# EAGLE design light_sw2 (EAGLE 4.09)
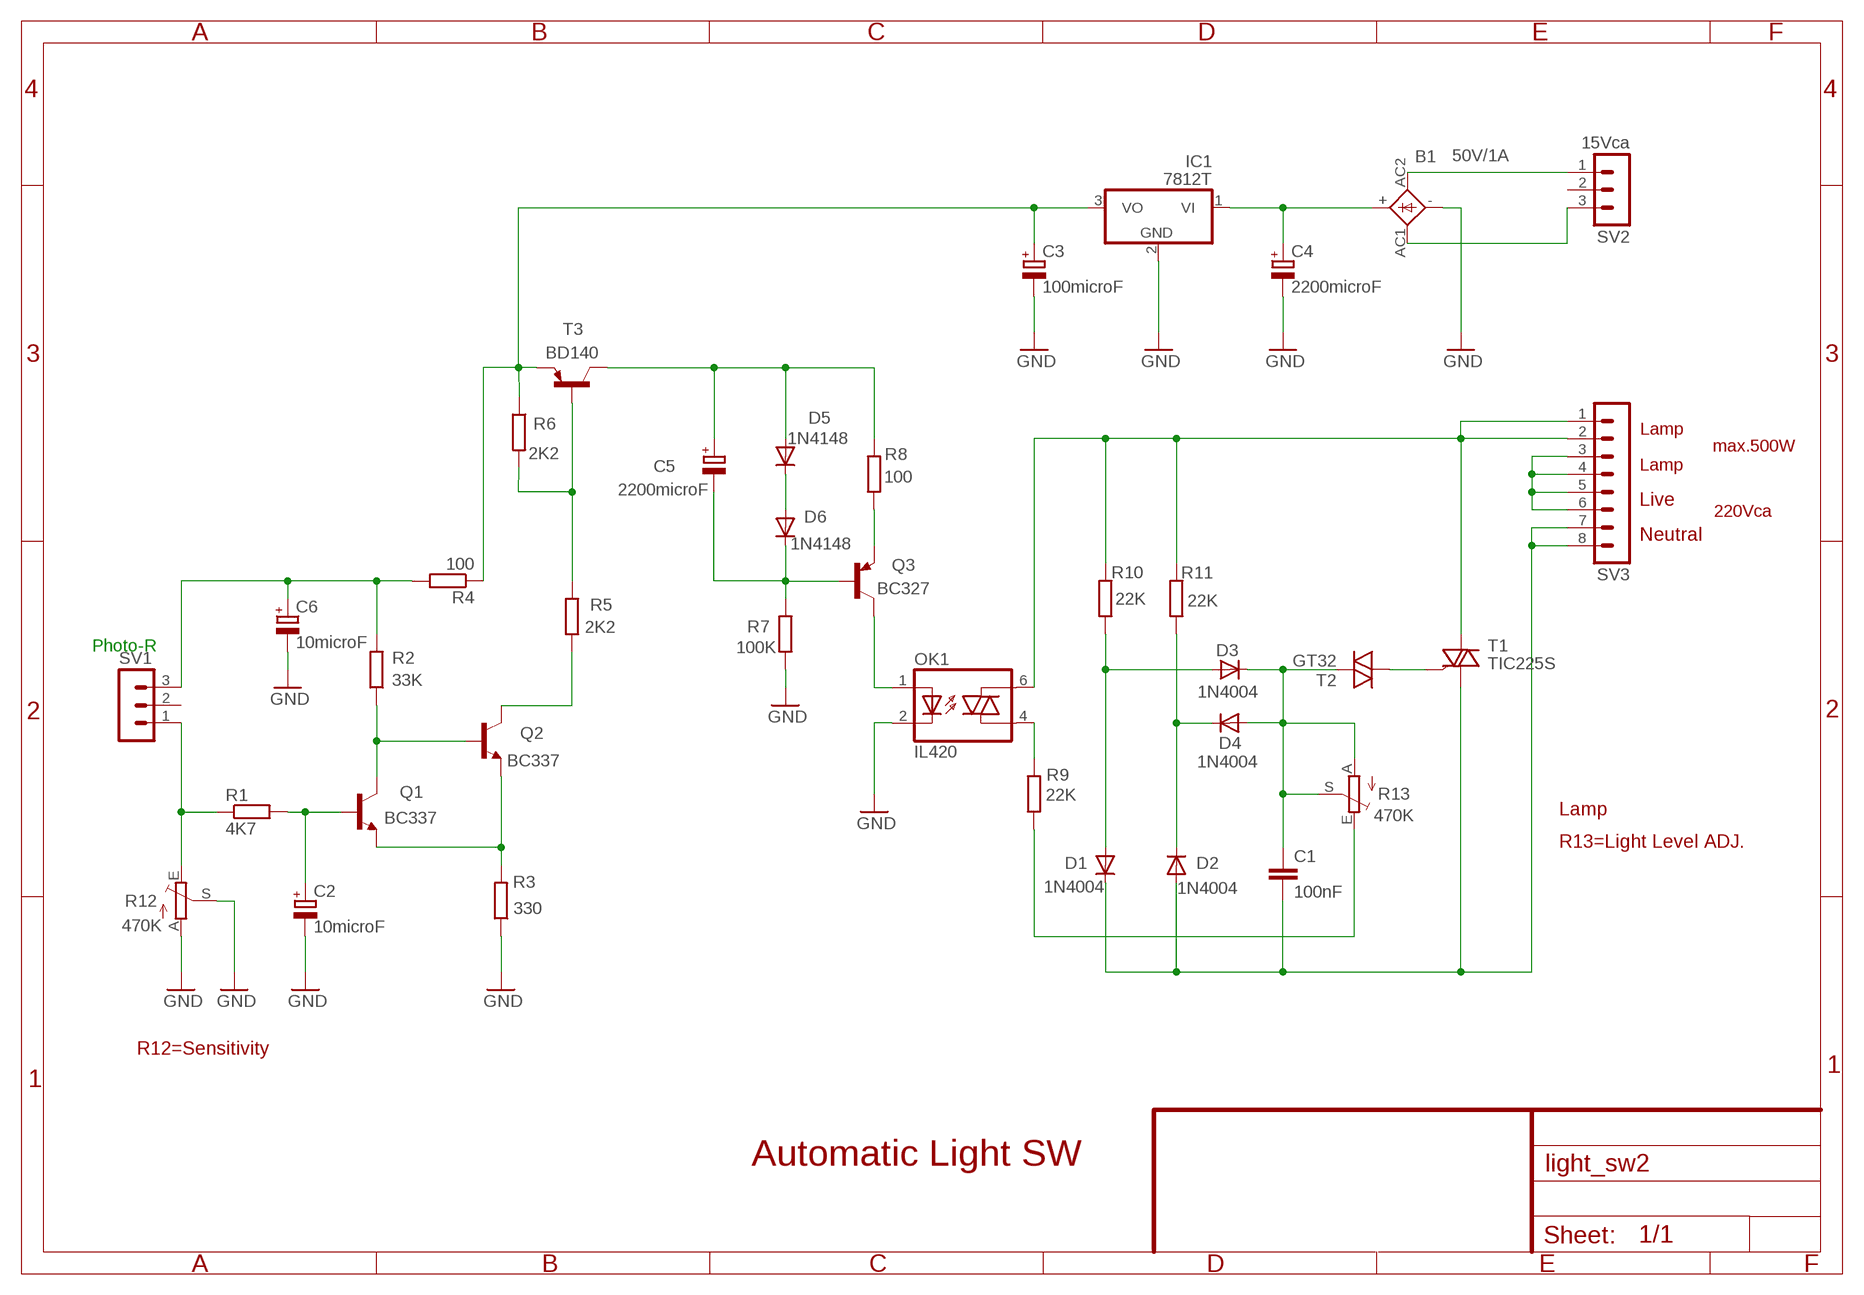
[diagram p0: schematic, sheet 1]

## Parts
B1  50V/1A  2KBP  [2KBP]
C1  100nF  C-EU050-045X075  [C050-045X075]
C2  10microF  CPOL-EUB45181A  [B45181A]
C3  100microF  CPOL-EUB45181A  [B45181A]
C4  2200microF  CPOL-EUB45181D  [B45181D]
C5  2200microF  CPOL-EUB45181D  [B45181D]
C6  10microF  CPOL-EUB45181A  [B45181A]
D1  1N4004  [DO41-10]
D2  1N4004  [DO41-10]
D3  1N4004  [DO41-10]
D4  1N4004  [DO41-10]
D5  1N4148  [DO35-10]
D6  1N4148  [DO35-10]
IC1  7812T  [TO220H]
OK1  IL420  [DIL06]
Q1  BC337  [TO92]
Q2  BC337  [TO92]
Q3  BC327  [TO92-EBC]
R1  4K7  R-EU_0207/7  [0207/7]
R2  33K  R-EU_0207/7  [0207/7]
R3  330  R-EU_0207/7  [0207/7]
R4  100  R-EU_0207/7  [0207/7]
R5  2K2  R-EU_0207/7  [0207/7]
R6  2K2  R-EU_0207/7  [0207/7]
R7  100K  R-EU_0207/7  [0207/7]
R8  100  R-EU_0207/7  [0207/7]
R9  22K  R-EU_0207/7  [0207/7]
R10  22K  R-EU_0207/7  [0207/7]
R11  22K  R-EU_0207/7  [0207/7]
R12  470K  TRIM_EU-LI10  [LI10]
R13  470K  TRIM_EU-LI10  [LI10]
SV1  MA03-1  [MA03-1]
SV2  15Vca  MA03-1  [MA03-1]
SV3  MA08-1  [MA08-1]
T1  TIC225S  [TO220DS]
T2  GT32  [GT32]
T3  BD140  [TO126]

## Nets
GND: B1.- C2.- C3.- C4.- C6.- IC1.2(GND) OK1.2(C) R3.1 R7.1 R12.A R12.S
N$1: C6.+ R2.2 R4.2 SV1.3
N$2: Q1.3(C) Q2.2(B) R2.1
N$3: Q2.3(C) R5.2
N$4: R5.1 R6.2 T3.3(B)
N$5: C3.+ IC1.3(VO) R4.1 R6.1 T3.1(E)
N$6: Q1.1(E) Q2.1(E) R3.2
N$7: C2.+ Q1.2(B) R1.2
N$8: R1.1 R12.E SV1.1
N$9: OK1.6(A2) R10.2 R11.2 SV3.1 SV3.2 T1.A2
N$10: SV3.3 SV3.4 SV3.5 SV3.6
N$11: B1.+ C4.+ IC1.1(VI)
N$13: B1.AC2 SV2.1
N$14: B1.AC1 SV2.3
N$15: T1.G T2.1
N$16: C5.+ D5.A R8.2 T3.2(C)
N$17: D5.C D6.A
N$18: Q3.E R8.1
N$19: C5.- D6.C Q3.B R7.2
N$20: OK1.1(A) Q3.C
N$21: OK1.4(A1) R9.2
N$22: D1.A D3.A R10.1
N$23: D2.C D4.C R11.1
N$24: C1.1 D3.C D4.A R13.A R13.S T2.2
N$25: R9.1 R13.E
N$26: C1.2 D1.C D2.A SV3.7 SV3.8 T1.A1
Unconnected: SV1.2 SV2.2

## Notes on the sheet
- Lamp
- max.500W
- Lamp
- Live
- 220Vca
- Neutral
- Photo-R
- Lamp
- R13=Light Level ADJ.
- R12=Sensitivity
- Automatic Light SW

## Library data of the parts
B1 = rectifier:2KBP: RECTIFIER grid 3 x 3,81 mm
C1 = rcl:C-EU: CAPACITOR, European symbol
C2-C6 = rcl:CPOL-EU: POLARIZED CAPACITOR, European symbol
D1-D4 = diode:1N4004: DIODE
D5 D6 = diode:1N4148: DIODE
IC1 = linear:78*: Positive VOLTAGE REGULATOR
OK1 = optocoupler:IL420: SIEMENS OPTO COUPLER
Q1 Q2 = transistor-npn:BC337*: NPN Transistor
Q3 = transistor-pnp:BC327*: PNP Transistror
R1-R11 = rcl:R-EU_: RESISTOR, European symbol
R12 R13 = pot:TRIM_EU-: POTENTIOMETER
SV1 SV2 = con-lstb:MA03-1: PIN HEADER
SV3 = con-lstb:MA08-1: PIN HEADER
T1 = triac:TIC225S: TRIAC
T2 = triac:GT32: TRIGGER DIODE
T3 = transistor-pnp:BD140: PNP Transistor

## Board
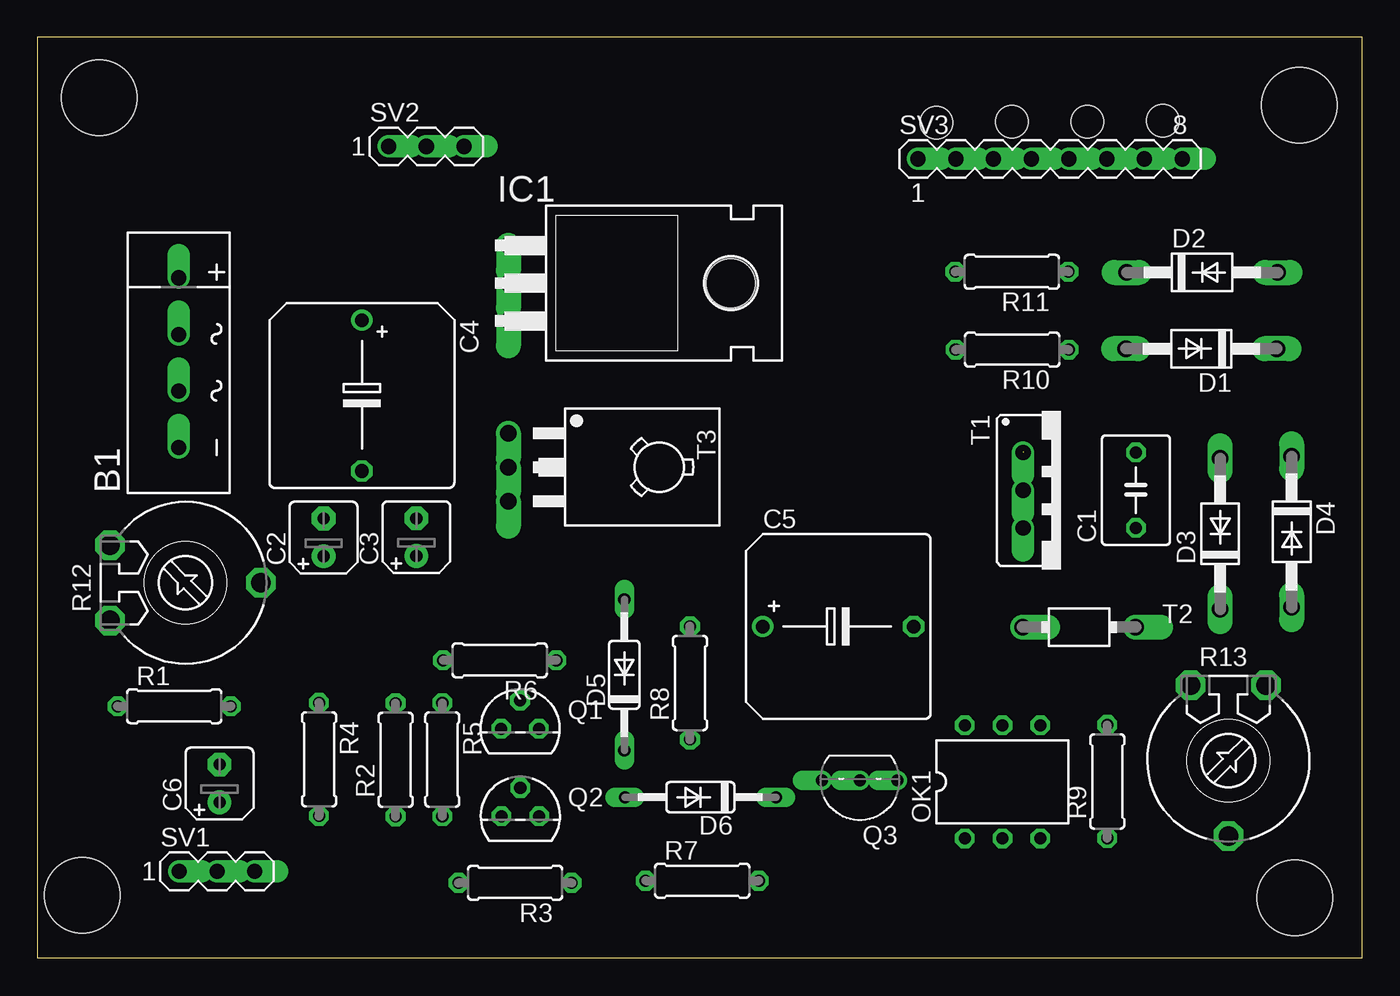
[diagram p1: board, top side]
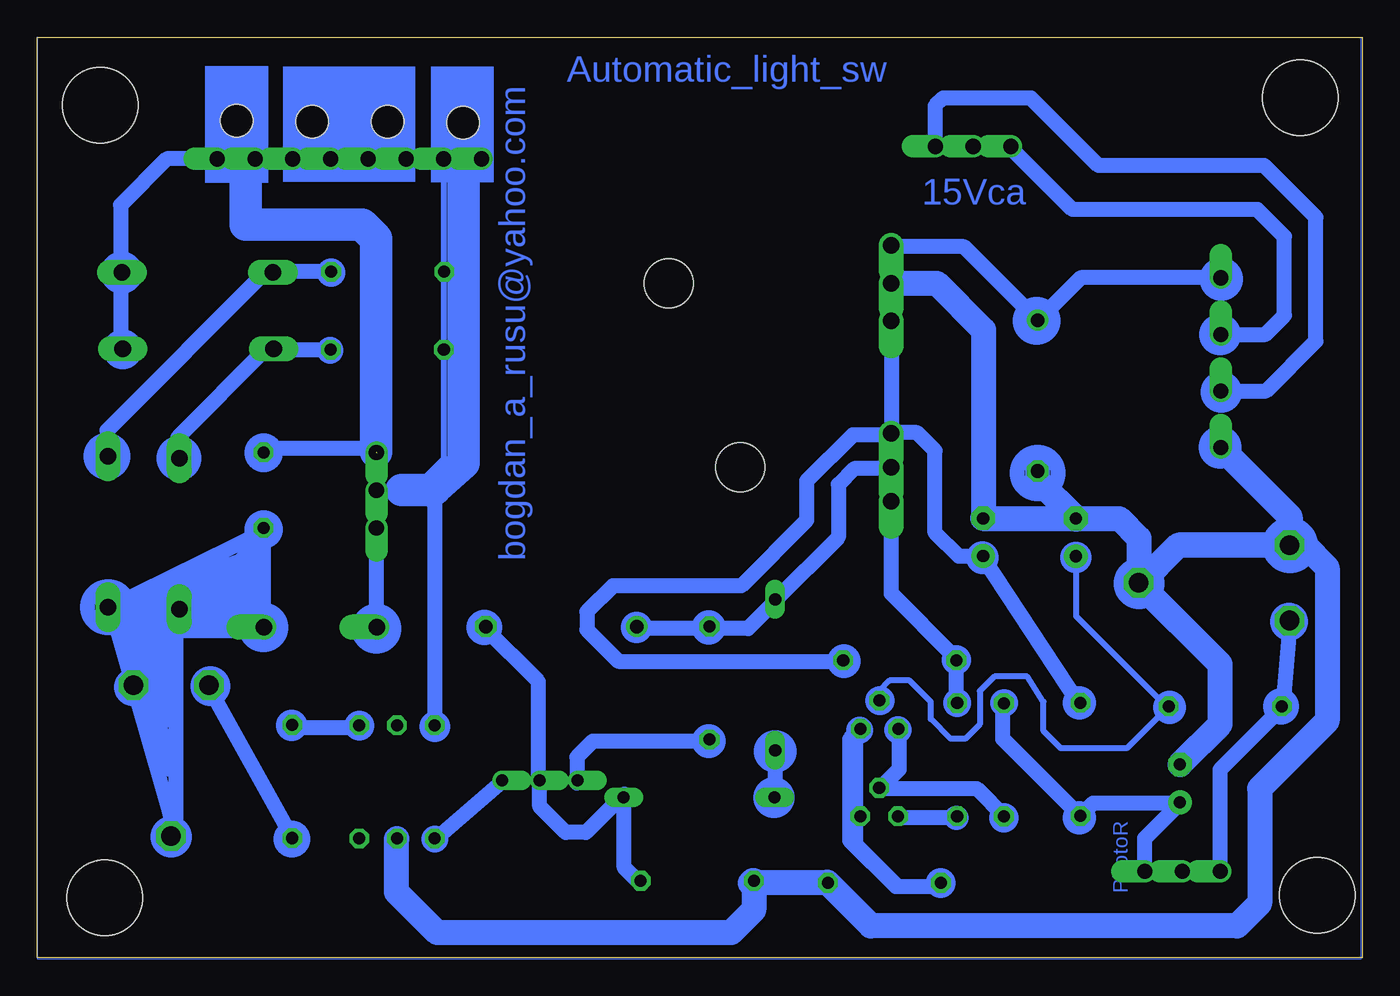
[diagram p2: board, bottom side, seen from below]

Size 89.23 x 61.98 mm. Coordinates in mm from the lower left corner, seen from the top.
Outline: 0,0 89.23,0 89.23,61.98 0,61.98 0,0
Copper layers used: Bottom
Holes 5.08 mm at 4.19,57.91 84.97,57.42 3.04,4.21 84.68,4.06
Holes 2.18 mm at 60.55,56.24 65.64,56.31 70.72,56.31 75.8,56.39

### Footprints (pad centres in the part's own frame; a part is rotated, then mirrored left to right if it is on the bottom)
2KBP = drill 1.016 offset: + 5.715,0; - -5.715,0; AC1 -1.905,0; AC2 1.905,0
C050-045X075 = drill 0.813 octagon: 1 -2.54,0; 2 2.54,0
B45181A = drill 0.813 pad 1.6 round: + -1.27,0 | drill 0.813 pad 1.6 octagon: - 1.27,0
B45181D = drill 0.914 round: + -5.08,0 | drill 0.914 octagon: - 5.08,0
DO41-10 = drill 1.118 long: A 5.08,0; C -5.08,0
DO35-10 = drill 0.813 long: A 5.08,0; C -5.08,0
TO220H = drill 1.118 offset: 1 -2.54,-10.16; 2 0,-10.16; 3 2.54,-10.16 | hole 3.302: 0,4.826
DIL06 = drill 0.813 octagon: 1 -2.54,-3.81; 2 0,-3.81; 3 2.54,-3.81; 4 2.54,3.81; 5 0,3.81; 6 -2.54,3.81
TO92 = drill 0.813 octagon: 1 1.27,0; 2 0,1.905; 3 -1.27,0
TO92-EBC = drill 0.813 offset: B 0,-1.27; C -2.54,-1.27; E 2.54,-1.27
0207/7 = drill 0.813 octagon: 1 -3.81,0; 2 3.81,0
LI10 = drill 1.321 octagon: A -2.54,-5.08; E 2.54,-5.08; S 0,5.08
MA03-1 = drill 1.016 offset: 1 -2.54,0; 2 0,0; 3 2.54,0
MA08-1 = drill 1.016 offset: 1 -8.89,0; 2 -6.35,0; 3 -3.81,0; 4 -1.27,0; 5 1.27,0; 6 3.81,0; 7 6.35,0; 8 8.89,0
TO220DS = drill 1.016 offset: A1 -2.54,-2.54; A2 0,-2.54; G 2.54,-2.54
GT32 = drill 1.118 offset: 1 -3.81,0; 2 3.81,0
TO126 = drill 1.118 offset: 1 -2.286,-5.08; 2 0,-5.08; 3 2.286,-5.08 | hole 3.302: 0,5.08

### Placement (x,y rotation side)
B1  9.54,40.08 90 top
C1  73.98,31.5 90 top
C2  19.28,28.31 90 top
C3  25.53,28.33 90 top
C4  21.87,37.86 270 top
C5  53.94,22.31 0 top
C6  12.28,11.75 90 top
D1  78.39,41.02 180 top
D2  78.44,46.16 0 top
D3  79.65,28.56 90 top
D4  84.47,28.69 270 top
D5  39.53,19.06 90 top
D6  44.66,10.82 180 top
IC1  41.89,45.43 270 top
OK1  65,11.85 0 top
Q1  32.52,15.43 0 top
Q2  32.53,9.54 0 top
Q3  55.39,10.67 180 top
R1  9.23,16.95 0 top
R2  24.14,13.34 90 top
R3  32.18,5.05 180 top
R4  18.98,13.37 270 top
R5  27.28,13.35 270 top
R6  31.14,20.04 180 top
R7  44.78,5.19 0 top
R8  43.96,18.51 90 top
R9  72.05,11.88 90 top
R10  65.65,40.96 180 top
R11  65.62,46.2 180 top
R12  9.98,25.26 270 top
R13  80.21,13.28 180 top
SV1  12.11,5.83 0 top
SV2  26.2,54.64 0 top
SV3  68.21,53.8 0 top
T1  68.93,31.49 270 top
T2  70.16,22.27 0 top
T3  36.81,33.04 270 top

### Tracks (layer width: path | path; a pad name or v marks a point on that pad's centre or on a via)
GND
  Bottom 1.676: IC1.2 28.66,45.43 25.5,42.28 25.5,29.68 25.58,29.61 25.57,29.6 C3.- 19.35,29.6 19.28,29.53 19.28,29.54 C2.- | C2.- 16.38,29.58 15.04,28.24 15.04,25.21 | 15.04,25.21 15.06,25.24 R12.S | 15.04,25.21 14.96,25.13 | 4.87,27.71 4.87,27.77 | 4.87,27.77 R12.A 12.37,27.8 12.38,27.79 | B1.- 4.87,29.7 4.87,27.77 | R12.S 15.06,25.16 15.04,25.13 12.38,27.79 | C2.- 19.28,29.61 21.87,32.2 C4.- | R12.S 9.57,19.77 9.57,19.75 | C6.- 9.57,15.73 9.57,19.75 | 9.57,19.75 15.04,25.21 | 15.04,25.21 14.96,25.21 12.38,27.79 | 12.38,27.79 3.88,27.79 2.37,26.27 2.37,15.95 6.92,11.4 6.92,3.66 8.44,2.15 33.09,2.15 R3.1 | 36.05,5.11 R3.1 | R3.1 41.19,5.05 | 41.19,5.05 41.05,5.19 R7.1 40.97,3.22 42.5,1.69 62.3,1.69 65.03,4.42 65.03,7.99 65,8.02 OK1.2 | 41.19,5.05 41.21,5.03
N$1
  Bottom 0.406: SV1.3 14.65,8.18 12.32,10.51 C6.+ 18.04,10.48 18.98,9.53 | 19.03,9.49 18.98,9.53 | 18.98,9.53 R4.2 24.14,14.72 R2.2 | 24.14,17.18 R2.2 | R2.2
N$2
  Bottom 0.406: R2.1 26.05,11.45 Q2.2 31.24,12.74 Q1.3
N$3
  Bottom 0.406: Q2.3 31.23,9.51 27.32,9.51 R5.2
N$4
  Bottom 0.406: 27.34,20.06 R6.2 | R6.2 31.75,24.45 31.75,30.74 T3.3 | R5.1 27.28,20 R6.2
N$5
  Bottom 0.406: R4.1 25.6,27.07 C3.+ 27.31,27.06 28.75,28.5 28.75,34.04 30.04,35.33 31.71,35.33 31.73,35.31 | 31.74,35.3 31.73,35.31 | 31.73,35.31 T3.1 | 31.73,35.22 31.73,35.23 T3.1 | IC1.3 31.73,35.22 | 31.73,35.22 31.72,35.22 | R6.1 50.15,20.04 52.21,22.1 52.21,23.31 50.31,25.21 41.66,25.21 37.34,29.53 37.34,32.11 34.15,35.3 31.72,35.3 31.73,35.31 T3.1
  Bottom 1.016: 31.72,42.81 31.72,35.22 34.3,35.22 37.41,32.11 37.41,29.46 41.81,25.06 50.46,25.06 52.21,23.31 52.21,22.1 50.08,19.97 34.91,19.97
N$6
  Bottom 0.406: R3.2 31.1,5.05 33.79,7.74 33.79,9.55 Q2.1 33.8,15.31 33.79,15.33 Q1.1
N$7
  Bottom 0.406: C2.+ 19.28,23.02 13.07,16.8 13.04,16.83 R1.2 15.87,14.12 20.31,14.12 | 20.31,14.12 | 20.31,14.12 21.47,15.28 21.47,17.25 22.56,18.95 24.77,18.95 25.76,17.96 25.76,15.73 26.74,14.75 27.72,14.75 29.06,16.09 29.06,17.25 30.49,18.68 31.83,18.68 32.52,17.99 Q1.2
N$8
  Bottom 0.406: SV1.1 9.57,12.69 5.37,16.89 R1.1 4.81,22.6 R12.E
N$9
  Bottom 0.406: OK1.6 62.46,30.15 63.81,31.51 66.17,31.51 66.39,31.29 | 66.39,31.29 66.39,31.28 | 66.39,31.29 T1.A2 63.99,31.49 61.84,33.63 61.84,40.84 R10.2 | R10.2 61.84,46.22 | 61.84,46.22 | 61.77,53.8 61.77,53.81 | 61.77,53.8 SV3.2 59.19,53.8 | 61.84,46.22 61.84,53.73 61.77,53.8 | 59.19,53.8 SV3.1 | 59.19,53.8 59.19,53.81 | 61.79,46.2 61.77,46.22 | 61.79,46.2 R11.2 | R10.2 61.84,46.15 61.79,46.2
N$10
  Bottom 0.406: SV3.3 66.78,53.8 66.93,53.66 66.94,53.67 SV3.4 69.28,53.8 69.35,53.73 69.42,53.8 SV3.5 72,53.8 72.01,53.81 SV3.6
N$11
  Bottom 1.016: B1.+ 18.95,45.79 21.81,42.94 C4.+ 26.82,47.89 31.72,47.89 IC1.1
N$12
  Bottom 2.184: 60.52,52.14 60.52,33.33 62.37,31.66 62.55,31.51 64.7,31.51
N$13
  Bottom 1.016: B1.AC2 6.53,41.98 5.25,43.27 5.25,48.58 7.07,50.4 19.51,50.4 23.68,54.57 23.66,54.59 SV2.1
N$14
  Bottom 1.016: B1.AC1 6.47,38.17 3.12,41.52 3.12,49.87 6.61,53.35 17.77,53.35 22.32,57.91 28.24,57.91 28.77,57.38 28.77,54.64 28.74,54.62 | 28.69,54.57 28.74,54.62 | 28.74,54.62 SV2.3
N$15
  Bottom 0.406: T2.1 66.33,22.25 66.32,22.25 66.32,28.88 T1.G
N$16
  Bottom 0.406: 43.72,22.29 43.93,22.29 | 43.93,22.29 R8.2 41.21,22.32 39.5,24.03 39.53,24.06 D5.A 35.41,28.27 35.41,31.66 34.04,33.03 33.61,33.03 33.55,32.97 31.81,32.97 T3.2 | C5.+ 48.83,22.29 43.93,22.29
N$17
  Bottom 0.406: D6.A 39.56,10.81 39.53,10.83 D5.C
N$18
  Bottom 0.406: R8.1 51.88,14.7 52.86,13.72 Q3.E
N$19
  Bottom 0.406: 49.7,10.87 49.7,10.85 | 49.7,10.85 D6.C 52.22,8.34 53.41,8.34 55.4,10.33 Q3.B | R7.2 49.7,6.31 49.7,10.85 | Q3.B | Q3.B | 55.4,11.91 Q3.B | C5.- 55.4,18.69 Q3.B
N$20
  Bottom 0.406: OK1.1 62.6,7.91 Q3.C
N$21
  Bottom 0.406: 72.05,15.61 72.08,15.58 | 72.05,15.61 R9.2 | OK1.4 72,15.66 72.05,15.61
N$22
  Bottom 0.406: 73.31,40.91 73.37,40.84 | 73.31,40.91 D1.A 73.72,41.02 79.67,35.07 79.67,33.55 | R10.1 73.25,40.96 73.31,40.91 | 79.67,33.55 79.65,33.57 D3.A | 79.67,33.55 79.75,33.48
N$23
  Bottom 0.406: D2.C 73.45,46.07 | D2.C 73.59,46.16 84.45,35.3 84.45,33.78 D4.C | R11.1 73.32,46.2 D2.C | D4.C 84.53,33.71 | D4.C
N$24
  Bottom 0.406: R13.S 82.78,18.31 R13.A 82.86,18.31 D4.A 84.53,23.46 C1.1 73.98,28.85 T2.2 73.91,22.18 D3.C
N$25
  Bottom 0.406: R13.E 77.7,18.31 R9.1
N$26  (1 unrouted)
  Bottom 0.406: SV3.8 77.08,53.8 SV3.7 77.17,53.8 77.24,53.73 80.66,53.73 83.54,50.85 83.54,46 83.52,45.98 | SV3.8 | T1.A1 73.89,34.03 | 83.52,45.98 83.46,45.92 83.47,40.93 D1.C 83.51,41.06 83.51,50.7 80.53,53.68 80.5,53.68 80.47,53.71 75.2,53.71 75.2,53.69 75.19,53.68 | 83.52,45.98 D2.A | 66.39,34.05 C1.2
  Bottom 2.184: 66.39,34.05 66.39,48.43 67.34,49.38 75.19,49.38 75.19,53.68
N$27
  Bottom 1.016: 9.57,5.71 9.57,12.69 5.33,16.94 4.87,22.48
N$28
  Bottom 1.016: 31.72,32.95 34.23,32.95 35.29,31.88 35.29,28.32 39.62,24 39.62,23.92 41.36,22.18 48.95,22.18
N$29
  Bottom 1.016: 27.32,17.09 27.32,19.97 27.48,20.13 27.48,20.28 31.72,24.53 31.72,30.82
N$30
  Bottom 1.016: 18.98,17.02 25.58,27.03 27.17,27.03 28.77,28.62 28.77,34.16 29.98,35.38 31.8,35.38
N$31
  Bottom 1.016: 14.66,5.79 14.66,8.06 12.31,10.42 18.15,10.42 19.06,9.51 19.06,9.58 24.21,14.74 24.21,17.17
N$32
  Bottom 1.016: 31.19,15.42 31.19,12.69 32.48,11.4 25.96,11.4 24.06,9.51
N$33
  Bottom 1.016: 27.25,9.43 31.27,9.43 31.42,9.58
N$34
  Bottom 1.016: 33.92,15.35 34.53,14.74 34.53,7.91 31.42,4.8 28.61,4.8
N$35
  Bottom 1.016: 39.54,14.06 39.54,10.72
N$36
  Bottom 1.016: 43.94,14.59 51.83,14.59 52.89,13.53 52.89,11.78
N$37
  Bottom 1.016: 48.64,5.03 49.7,6.09 49.7,11.02 52.28,8.44 53.65,8.44 55.39,10.19 55.39,12.01 55.47,12.09 55.47,18.61 59.19,22.33
N$38
  Bottom 1.016: 57.97,11.86 62.45,7.99
N$39
  Bottom 1.016: 62.45,15.58 62.45,30.97
N$40
  Bottom 1.016: 67.53,15.5 72.16,15.5
N$41
  Bottom 1.016: 77.77,18.38 71.93,7.84
N$42
  Bottom 1.016: 66.39,28.93 66.39,22.25
N$43
  Bottom 1.016: 66.24,34.31 73.98,34.31
N$44
  Bottom 1.016: 77.85,53.81 80.5,53.81 83.61,50.7 83.61,41.07 83.54,40.99
N$45
  Bottom 1.016: 69.43,46.22 73.83,46.22 84.53,35.53 84.53,33.78 84.6,33.71
N$46
  Bottom 1.016: 69.35,40.91 73.91,40.91 79.75,35.07 79.75,33.71
N$47
  Bottom 1.016: 79.68,23.4 73.99,22.27 73.99,28.72 84.46,23.55 73.99,22.19 82.33,23.93 74.44,23.1 81.2,24.47 74.29,24.01 79.68,25 74.59,24.85 78.92,25.45 74.29,25.23 78.16,25.91 74.52,26.06 76.49,26.44 74.44,27.12 75.28,27.43 74.75,27.5 79.91,22.87 79.91,8.37 84.23,23.48 80.36,22.27 83.09,22.19 80.36,12.7 82.18,21.81 80.74,21.81 80.66,15.96 81.58,21.43 83.3,22.52 80.08,24.98 76.98,26.38 79.57,22.77 79.99,22.06 74.24,22.06 74.01,22.15
N$48
  Bottom 0: 0.01,61.93 89.23,62 89.23,-0.05 0.09,-0.05 0.09,61.93
(copper drawn outside any net)
  shapes: Bottom area x3, Bottom circle x52

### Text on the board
Bottom: Automatic_light_sw | bogdan_a_rusu@yahoo.com | 15Vca | PhotoR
